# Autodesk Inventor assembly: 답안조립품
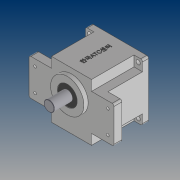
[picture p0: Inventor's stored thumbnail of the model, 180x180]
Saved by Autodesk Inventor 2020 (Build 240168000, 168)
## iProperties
Created: 2020-07
Part Number: 답안조립품
Document SubType Name: Assembly
Designer: PC312-
Author: PC312-
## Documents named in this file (10)
- C:\Users\PC312-\Desktop\700718V1003\답안조립품.iam
- C:\Users\PC312-\Desktop\700718V1003\본체.ipt
- C:\Users\PC312-\Desktop\700718V1003\커버.ipt
- C:\Users\PC312-\Desktop\700718V1003\오일 실 8 22 7.ipt
- C:\Users\PC312-\Desktop\700718V1003\베어링 608.ipt
- C:\Users\PC312-\Desktop\700718V1003\메인 축.ipt
- C:\Users\PC312-\Desktop\700718V1003\서브 축.ipt
- C:\Users\PC312-\Desktop\700718V1003\베어링 6003.ipt
- C:\Users\PC312-\Desktop\700718V1003\오일 실 17 32 8.ipt
- C:\Users\PC312-\Desktop\700718V1003\볼트 M4.ipt
